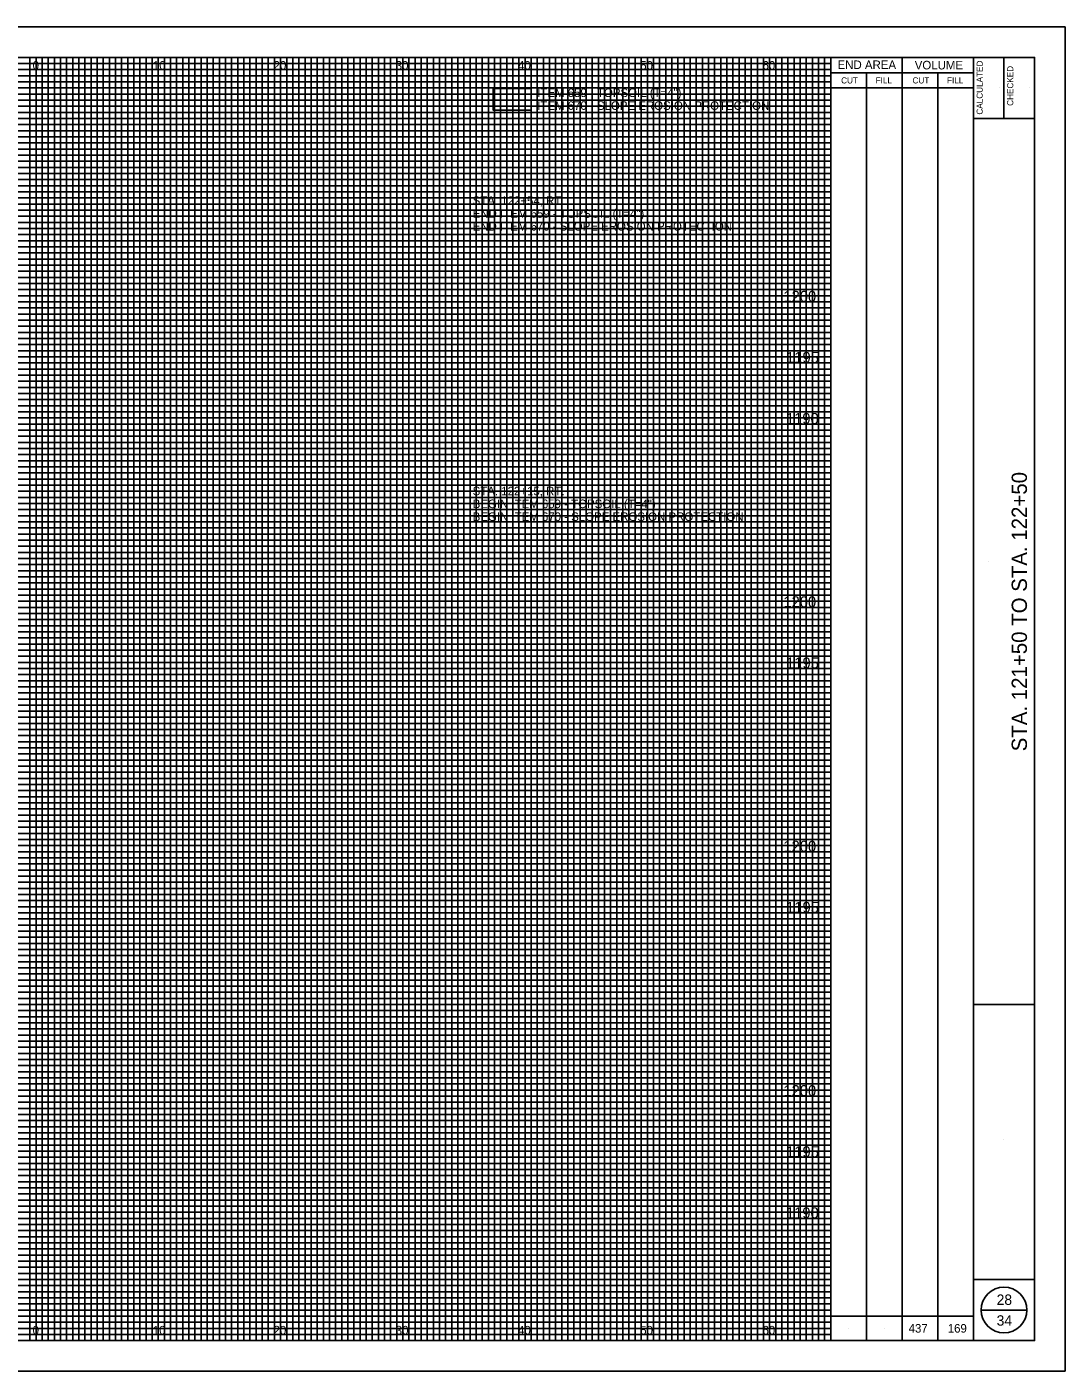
# Model space of a CAD drawing. Extents: x -10 to 160, y -13 to 1488.
# Drawn here: x 75.1 to 160, y 1262.5 to 1372.5 of the extents above; entities that cross this region are included whole.
import ezdxf

# ---------------------------------------------------------------- set-up
doc = ezdxf.new("R2010")
doc.units = 0
for name, color, linetype in [('DR_X_Storm_Sewer', 7, 'Continuous'), ('GK_Cells', 7, 'Continuous'), ('PF_P_Sta_Elev_Text', 7, 'Continuous'), ('PF_X_Ground_Line', 7, 'Continuous'), ('PV_P_EOP', 7, 'Continuous'), ('PV_P_Saw_Cut_Line', 7, 'Continuous'), ('PV_P_Shoulder', 7, 'Continuous'), ('XS_P_Pavt_Layers', 7, 'Continuous')]:
    doc.layers.add(name, color=color, linetype=linetype)

msp = doc.modelspace()

# ---------------------------------------------------------------- linework, layer by layer
at = {"layer": 'GK_Cells'}
for p, q in [((152.5, 1265), (152.5, 1370)), ((155, 1370), (155, 1365)), ((152.5, 1365), (157.5, 1365)), ((152.5, 1292.5), (157.5, 1292.5)), ((152.5, 1270), (157.5, 1270))]:
    msp.add_line(p, q, dxfattribs=at)
msp.add_lwpolyline([(0, 1370), (157.5, 1370), (157.5, 1265), (0, 1265)], close=True, dxfattribs=at)
at = {"layer": 'PF_P_Sta_Elev_Text'}
msp.add_lwpolyline([(-10, 1262.5), (160, 1262.5), (160, 1372.5), (-10, 1372.5)], close=True, dxfattribs=at)
at = {"layer": 'PF_X_Ground_Line'}
for p, q in [((140.83, 1265), (140.83, 1370)), ((146.67, 1265), (146.67, 1370)), ((140.83, 1368.75), (152.5, 1368.75)), ((143.75, 1265), (143.75, 1368.75)), ((149.58, 1265), (149.58, 1368.75)), ((140.83, 1367.5), (152.5, 1367.5)), ((154.6, 1367.52), (154.6, 1367.52)), ((157.1, 1367.52), (157.1, 1367.52)), ((153.75, 1328.75), (153.75, 1328.75)), ((156.26, 1328.75), (156.26, 1328.75)), ((155, 1281.46), (155, 1281.46)), ((153.12, 1267.5), (156.88, 1267.5)), ((155, 1267.92), (155, 1267.92)), ((140.83, 1267), (152.5, 1267)), ((155, 1266.22), (155, 1266.22)), ((142.29, 1266), (142.29, 1266)), ((145.21, 1266), (145.21, 1266)), ((148.12, 1266), (148.12, 1266)), ((151.04, 1266), (151.04, 1266))]:
    msp.add_line(p, q, dxfattribs=at)
msp.add_circle((155, 1267.5), 1.87, dxfattribs=at)
at = {"layer": 'PV_P_EOP'}
for p, q in [((5.83, 1369.5), (140.83, 1369.5)), ((75.33, 1265), (75.33, 1370)), ((76.33, 1265), (76.33, 1370)), ((76.83, 1265), (76.83, 1370)), ((77.33, 1265), (77.33, 1370)), ((77.83, 1265), (77.83, 1370)), ((78.33, 1265), (78.33, 1370)), ((78.83, 1265), (78.83, 1370)), ((79.33, 1265), (79.33, 1370)), ((79.83, 1265), (79.83, 1370)), ((80.33, 1265), (80.33, 1370)), ((81.33, 1265), (81.33, 1370)), ((81.83, 1265), (81.83, 1370)), ((82.33, 1265), (82.33, 1370)), ((82.83, 1265), (82.83, 1370)), ((83.33, 1265), (83.33, 1370)), ((83.83, 1265), (83.83, 1370)), ((84.33, 1265), (84.33, 1370)), ((84.83, 1265), (84.83, 1370)), ((85.33, 1265), (85.33, 1370)), ((86.33, 1265), (86.33, 1370)), ((86.83, 1265), (86.83, 1370)), ((87.33, 1265), (87.33, 1370)), ((87.83, 1265), (87.83, 1370)), ((88.33, 1265), (88.33, 1370)), ((88.83, 1265), (88.83, 1370)), ((89.33, 1265), (89.33, 1370)), ((89.83, 1265), (89.83, 1370)), ((90.33, 1265), (90.33, 1370)), ((91.33, 1265), (91.33, 1370)), ((91.83, 1265), (91.83, 1370)), ((92.33, 1265), (92.33, 1370)), ((92.83, 1265), (92.83, 1370)), ((93.33, 1265), (93.33, 1370)), ((93.83, 1265), (93.83, 1370)), ((94.33, 1265), (94.33, 1370)), ((94.83, 1265), (94.83, 1370)), ((95.33, 1265), (95.33, 1370)), ((96.33, 1265), (96.33, 1370)), ((96.83, 1265), (96.83, 1370)), ((97.33, 1265), (97.33, 1370)), ((97.83, 1265), (97.83, 1370)), ((98.33, 1265), (98.33, 1370)), ((98.83, 1265), (98.83, 1370)), ((99.33, 1265), (99.33, 1370)), ((99.83, 1265), (99.83, 1370)), ((100.33, 1265), (100.33, 1370)), ((101.33, 1265), (101.33, 1370)), ((101.83, 1265), (101.83, 1370)), ((102.33, 1265), (102.33, 1370)), ((102.83, 1265), (102.83, 1370)), ((103.33, 1265), (103.33, 1370)), ((103.83, 1265), (103.83, 1370)), ((104.33, 1265), (104.33, 1370)), ((104.83, 1265), (104.83, 1370)), ((105.33, 1265), (105.33, 1370)), ((106.33, 1265), (106.33, 1370)), ((106.83, 1265), (106.83, 1370)), ((107.33, 1265), (107.33, 1370)), ((107.83, 1265), (107.83, 1370)), ((108.33, 1265), (108.33, 1370)), ((108.83, 1265), (108.83, 1370)), ((109.33, 1265), (109.33, 1370)), ((109.83, 1265), (109.83, 1370)), ((110.33, 1265), (110.33, 1370)), ((111.33, 1265), (111.33, 1370)), ((111.83, 1265), (111.83, 1370)), ((112.33, 1265), (112.33, 1370)), ((112.83, 1265), (112.83, 1370)), ((113.33, 1265), (113.33, 1370)), ((113.83, 1265), (113.83, 1370)), ((114.33, 1265), (114.33, 1370)), ((114.83, 1265), (114.83, 1370)), ((115.33, 1265), (115.33, 1370)), ((116.33, 1265), (116.33, 1370)), ((116.83, 1265), (116.83, 1370)), ((117.33, 1265), (117.33, 1370)), ((117.83, 1265), (117.83, 1370)), ((118.33, 1265), (118.33, 1370)), ((118.83, 1265), (118.83, 1370)), ((119.33, 1265), (119.33, 1370)), ((119.83, 1265), (119.83, 1370)), ((120.33, 1265), (120.33, 1370)), ((121.33, 1265), (121.33, 1370)), ((121.83, 1265), (121.83, 1370)), ((122.33, 1265), (122.33, 1370)), ((122.83, 1265), (122.83, 1370)), ((123.33, 1265), (123.33, 1370)), ((123.83, 1265), (123.83, 1370)), ((124.33, 1265), (124.33, 1370)), ((124.83, 1265), (124.83, 1370)), ((125.33, 1265), (125.33, 1370)), ((126.33, 1265), (126.33, 1370)), ((126.83, 1265), (126.83, 1370)), ((127.33, 1265), (127.33, 1370)), ((127.83, 1265), (127.83, 1370)), ((128.33, 1265), (128.33, 1370)), ((128.83, 1265), (128.83, 1370)), ((129.33, 1265), (129.33, 1370)), ((129.83, 1265), (129.83, 1370)), ((130.33, 1265), (130.33, 1370)), ((131.33, 1265), (131.33, 1370)), ((131.83, 1265), (131.83, 1370)), ((132.33, 1265), (132.33, 1370)), ((132.83, 1265), (132.83, 1370)), ((133.33, 1265), (133.33, 1370)), ((133.83, 1265), (133.83, 1370)), ((134.33, 1265), (134.33, 1370)), ((134.83, 1265), (134.83, 1370)), ((135.33, 1265), (135.33, 1370)), ((136.33, 1265), (136.33, 1370)), ((136.83, 1265), (136.83, 1370)), ((137.33, 1265), (137.33, 1370)), ((137.83, 1265), (137.83, 1370)), ((138.33, 1265), (138.33, 1370)), ((138.83, 1265), (138.83, 1370)), ((139.33, 1265), (139.33, 1370)), ((139.83, 1265), (139.83, 1370)), ((140.33, 1265), (140.33, 1370)), ((5.83, 1369), (140.83, 1369)), ((5.83, 1368.5), (140.83, 1368.5)), ((5.83, 1368), (140.83, 1368)), ((5.83, 1367.5), (140.83, 1367.5)), ((5.83, 1367), (140.83, 1367)), ((5.83, 1366.5), (140.83, 1366.5)), ((5.83, 1366), (140.83, 1366)), ((5.83, 1365.5), (140.83, 1365.5)), ((5.83, 1364.5), (140.83, 1364.5)), ((5.83, 1364), (140.83, 1364)), ((5.83, 1363.5), (140.83, 1363.5)), ((5.83, 1363), (140.83, 1363)), ((5.83, 1362.5), (140.83, 1362.5)), ((5.83, 1362), (140.83, 1362)), ((5.83, 1361.5), (140.83, 1361.5)), ((5.83, 1361), (140.83, 1361)), ((5.83, 1360.5), (140.83, 1360.5)), ((5.83, 1359.5), (140.83, 1359.5)), ((5.83, 1359), (140.83, 1359)), ((5.83, 1358.5), (140.83, 1358.5)), ((5.83, 1358), (140.83, 1358)), ((5.83, 1357.5), (140.83, 1357.5)), ((5.83, 1357), (140.83, 1357)), ((5.83, 1356.5), (140.83, 1356.5)), ((5.83, 1356), (140.83, 1356)), ((5.83, 1355.5), (140.83, 1355.5)), ((5.83, 1354.5), (140.83, 1354.5)), ((5.83, 1354), (140.83, 1354)), ((5.83, 1353.5), (140.83, 1353.5)), ((5.83, 1353), (140.83, 1353)), ((5.83, 1352.5), (140.83, 1352.5)), ((5.83, 1352), (140.83, 1352)), ((5.83, 1351.5), (140.83, 1351.5)), ((5.83, 1351), (140.83, 1351)), ((5.83, 1350.5), (140.83, 1350.5)), ((5.83, 1349.5), (140.83, 1349.5)), ((5.83, 1349), (140.83, 1349)), ((5.83, 1348.5), (140.83, 1348.5)), ((5.83, 1348), (140.83, 1348)), ((5.83, 1347.5), (140.83, 1347.5)), ((5.83, 1347), (140.83, 1347)), ((5.83, 1346.5), (140.83, 1346.5)), ((5.83, 1346), (140.83, 1346)), ((5.83, 1345.5), (140.83, 1345.5)), ((5.83, 1344.5), (140.83, 1344.5)), ((5.83, 1344), (140.83, 1344)), ((5.83, 1343.5), (140.83, 1343.5)), ((5.83, 1343), (140.83, 1343)), ((5.83, 1342.5), (140.83, 1342.5)), ((5.83, 1342), (140.83, 1342)), ((5.83, 1341.5), (140.83, 1341.5)), ((5.83, 1341), (140.83, 1341)), ((5.83, 1340.5), (140.83, 1340.5)), ((5.83, 1339.5), (140.83, 1339.5)), ((5.83, 1339), (140.83, 1339)), ((5.83, 1338.5), (140.83, 1338.5)), ((5.83, 1338), (140.83, 1338)), ((5.83, 1337.5), (140.83, 1337.5)), ((5.83, 1337), (140.83, 1337)), ((5.83, 1336.5), (140.83, 1336.5)), ((5.83, 1336), (140.83, 1336)), ((5.83, 1335.5), (140.83, 1335.5)), ((5.83, 1334.5), (140.83, 1334.5)), ((5.83, 1334), (140.83, 1334)), ((5.83, 1333.5), (140.83, 1333.5)), ((5.83, 1333), (140.83, 1333)), ((5.83, 1332.5), (140.83, 1332.5)), ((5.83, 1332), (140.83, 1332)), ((5.83, 1331.5), (140.83, 1331.5)), ((5.83, 1331), (140.83, 1331)), ((5.83, 1330.5), (140.83, 1330.5)), ((5.83, 1329.5), (140.83, 1329.5)), ((5.83, 1329), (140.83, 1329)), ((5.83, 1328.5), (140.83, 1328.5)), ((5.83, 1328), (140.83, 1328)), ((5.83, 1327.5), (140.83, 1327.5)), ((5.83, 1327), (140.83, 1327)), ((5.83, 1326.5), (140.83, 1326.5)), ((5.83, 1326), (140.83, 1326)), ((5.83, 1325.5), (140.83, 1325.5)), ((5.83, 1324.5), (140.83, 1324.5)), ((5.83, 1324), (140.83, 1324)), ((5.83, 1323.5), (140.83, 1323.5)), ((5.83, 1323), (140.83, 1323)), ((5.83, 1322.5), (140.83, 1322.5)), ((5.83, 1322), (140.83, 1322)), ((5.83, 1321.5), (140.83, 1321.5)), ((5.83, 1321), (140.83, 1321)), ((5.83, 1320.5), (140.83, 1320.5)), ((5.83, 1319.5), (140.83, 1319.5)), ((5.83, 1319), (140.83, 1319)), ((5.83, 1318.5), (140.83, 1318.5)), ((5.83, 1318), (140.83, 1318)), ((5.83, 1317.5), (140.83, 1317.5)), ((5.83, 1317), (140.83, 1317)), ((5.83, 1316.5), (140.83, 1316.5)), ((5.83, 1316), (140.83, 1316)), ((5.83, 1315.5), (140.83, 1315.5)), ((5.83, 1314.5), (140.83, 1314.5)), ((5.83, 1314), (140.83, 1314)), ((5.83, 1313.5), (140.83, 1313.5)), ((5.83, 1313), (140.83, 1313)), ((5.83, 1312.5), (140.83, 1312.5)), ((5.83, 1312), (140.83, 1312)), ((5.83, 1311.5), (140.83, 1311.5)), ((5.83, 1311), (140.83, 1311)), ((5.83, 1310.5), (140.83, 1310.5)), ((5.83, 1309.5), (140.83, 1309.5)), ((5.83, 1309), (140.83, 1309)), ((5.83, 1308.5), (140.83, 1308.5)), ((5.83, 1308), (140.83, 1308)), ((5.83, 1307.5), (140.83, 1307.5)), ((5.83, 1307), (140.83, 1307)), ((5.83, 1306.5), (140.83, 1306.5)), ((5.83, 1306), (140.83, 1306)), ((5.83, 1305.5), (140.83, 1305.5)), ((5.83, 1304.5), (140.83, 1304.5)), ((5.83, 1304), (140.83, 1304)), ((5.83, 1303.5), (140.83, 1303.5)), ((5.83, 1303), (140.83, 1303)), ((5.83, 1302.5), (140.83, 1302.5)), ((5.83, 1302), (140.83, 1302)), ((5.83, 1301.5), (140.83, 1301.5)), ((5.83, 1301), (140.83, 1301)), ((5.83, 1300.5), (140.83, 1300.5)), ((5.83, 1299.5), (140.83, 1299.5)), ((5.83, 1299), (140.83, 1299)), ((5.83, 1298.5), (140.83, 1298.5)), ((5.83, 1298), (140.83, 1298)), ((5.83, 1297.5), (140.83, 1297.5)), ((5.83, 1297), (140.83, 1297)), ((5.83, 1296.5), (140.83, 1296.5)), ((5.83, 1296), (140.83, 1296)), ((5.83, 1295.5), (140.83, 1295.5)), ((5.83, 1294.5), (140.83, 1294.5)), ((5.83, 1294), (140.83, 1294)), ((5.83, 1293.5), (140.83, 1293.5)), ((5.83, 1293), (140.83, 1293)), ((5.83, 1292.5), (140.83, 1292.5)), ((5.83, 1292), (140.83, 1292)), ((5.83, 1291.5), (140.83, 1291.5)), ((5.83, 1291), (140.83, 1291)), ((5.83, 1290.5), (140.83, 1290.5)), ((5.83, 1289.5), (140.83, 1289.5)), ((5.83, 1289), (140.83, 1289)), ((5.83, 1288.5), (140.83, 1288.5)), ((5.83, 1288), (140.83, 1288)), ((5.83, 1287.5), (140.83, 1287.5)), ((5.83, 1287), (140.83, 1287)), ((5.83, 1286.5), (140.83, 1286.5)), ((5.83, 1286), (140.83, 1286)), ((5.83, 1285.5), (140.83, 1285.5)), ((5.83, 1284.5), (140.83, 1284.5)), ((5.83, 1284), (140.83, 1284)), ((5.83, 1283.5), (140.83, 1283.5)), ((5.83, 1283), (140.83, 1283)), ((5.83, 1282.5), (140.83, 1282.5)), ((5.83, 1282), (140.83, 1282)), ((5.83, 1281.5), (140.83, 1281.5)), ((5.83, 1281), (140.83, 1281)), ((5.83, 1280.5), (140.83, 1280.5)), ((5.83, 1279.5), (140.83, 1279.5)), ((5.83, 1279), (140.83, 1279)), ((5.83, 1278.5), (140.83, 1278.5)), ((5.83, 1278), (140.83, 1278)), ((5.83, 1277.5), (140.83, 1277.5)), ((5.83, 1277), (140.83, 1277)), ((5.83, 1276.5), (140.83, 1276.5)), ((5.83, 1276), (140.83, 1276)), ((5.83, 1275.5), (140.83, 1275.5)), ((5.83, 1274.5), (140.83, 1274.5)), ((5.83, 1274), (140.83, 1274)), ((5.83, 1273.5), (140.83, 1273.5)), ((5.83, 1273), (140.83, 1273)), ((5.83, 1272.5), (140.83, 1272.5)), ((5.83, 1272), (140.83, 1272)), ((5.83, 1271.5), (140.83, 1271.5)), ((5.83, 1271), (140.83, 1271)), ((5.83, 1270.5), (140.83, 1270.5)), ((5.83, 1269.5), (140.83, 1269.5)), ((5.83, 1269), (140.83, 1269)), ((5.83, 1268.5), (140.83, 1268.5)), ((5.83, 1268), (140.83, 1268)), ((5.83, 1267.5), (140.83, 1267.5)), ((5.83, 1267), (140.83, 1267)), ((5.83, 1266.5), (140.83, 1266.5)), ((5.83, 1266), (140.83, 1266)), ((5.83, 1265.5), (140.83, 1265.5))]:
    msp.add_line(p, q, dxfattribs=at)
at = {"layer": 'PV_P_Saw_Cut_Line'}
msp.add_lwpolyline([(113.21, 1367.47), (116.32, 1367.47), (116.32, 1365.69), (113.21, 1365.69)], close=True, dxfattribs=at)
msp.add_lwpolyline([(113.21, 1365.69), (116.32, 1365.69), (116.32, 1367.47), (113.21, 1367.47), (113.21, 1365.69)], dxfattribs=at)
at = {"layer": 'PV_P_Shoulder'}
for p, q in [((75.83, 1265), (75.83, 1370)), ((80.83, 1265), (80.83, 1370)), ((85.83, 1265), (85.83, 1370)), ((90.83, 1265), (90.83, 1370)), ((95.83, 1265), (95.83, 1370)), ((100.83, 1265), (100.83, 1370)), ((105.83, 1265), (105.83, 1370)), ((110.83, 1265), (110.83, 1370)), ((115.83, 1265), (115.83, 1370)), ((120.83, 1265), (120.83, 1370)), ((125.83, 1265), (125.83, 1370)), ((130.83, 1265), (130.83, 1370)), ((135.83, 1265), (135.83, 1370)), ((11.66, 1365), (140.83, 1365)), ((11.66, 1360), (140.83, 1360)), ((11.66, 1355), (140.83, 1355)), ((11.66, 1350), (140.83, 1350)), ((11.66, 1345), (140.83, 1345)), ((11.66, 1340), (140.83, 1340)), ((11.66, 1335), (140.83, 1335)), ((11.66, 1330), (140.83, 1330)), ((11.66, 1325), (140.83, 1325)), ((11.66, 1320), (140.83, 1320)), ((11.66, 1315), (140.83, 1315)), ((11.66, 1310), (140.83, 1310)), ((11.66, 1305), (140.83, 1305)), ((11.66, 1300), (140.83, 1300)), ((11.66, 1295), (140.83, 1295)), ((11.66, 1290), (140.83, 1290)), ((11.66, 1285), (140.83, 1285)), ((11.66, 1280), (140.83, 1280)), ((11.66, 1275), (140.83, 1275)), ((11.66, 1270), (140.83, 1270))]:
    msp.add_line(p, q, dxfattribs=at)

# ---------------------------------------------------------------- texts
at = {"layer": 'DR_X_Storm_Sewer'}
for s, height, p in [('0', 0.7, (75.55, 1369)), ('0', 0.7, (75.55, 1369)), ('10', 0.7, (85.39, 1369)), ('20', 0.7, (95.26, 1369)), ('30', 0.7, (105.25, 1369)), ('40', 0.7, (115.25, 1369)), ('50', 0.7, (125.25, 1369)), ('60', 0.7, (135.25, 1369)), ('1200', 0.9, (136.96, 1350)), ('1195', 0.9, (137.18, 1345)), ('1190', 0.9, (137.17, 1340)), ('1200', 0.9, (136.96, 1325)), ('1195', 0.9, (137.18, 1320)), ('1200', 0.9, (136.96, 1305)), ('1195', 0.9, (137.18, 1300)), ('1200', 0.9, (136.96, 1285)), ('1195', 0.9, (137.18, 1280)), ('1190', 0.9, (137.17, 1275)), ('28', 0.85, (154.4, 1267.92)), ('0', 0.7, (75.55, 1265.5)), ('0', 0.7, (75.55, 1265.5)), ('10', 0.7, (85.39, 1265.5)), ('20', 0.7, (95.26, 1265.5)), ('30', 0.7, (105.25, 1265.5)), ('40', 0.7, (115.25, 1265.5)), ('50', 0.7, (125.25, 1265.5)), ('60', 0.7, (135.25, 1265.5)), ('437', 0.7, (147.2, 1265.65)), ('169', 0.7, (150.4, 1265.65)), ('34', 0.85, (154.4, 1266.22))]:
    msp.add_text(s, height=height, dxfattribs=at).set_placement(p)
at = {"layer": 'PF_X_Ground_Line'}
for s, height, p in [('END AREA', 0.7, (141.39, 1369.05)), ('VOLUME', 0.7, (147.7, 1369.02)), ('CUT', 0.5, (141.68, 1367.87)), ('FILL', 0.5, (144.5, 1367.87)), ('CUT', 0.5, (147.52, 1367.87)), ('FILL', 0.5, (150.34, 1367.87))]:
    msp.add_text(s, height=height, dxfattribs=at).set_placement(p)
for s, height, p in [('CALCULATED', 0.5, (153.26, 1365.32)), ('CHECKED', 0.5, (155.76, 1366.04)), ('STA. 121+50 TO STA. 122+50', 1.25, (156.88, 1313.22))]:
    msp.add_text(s, height=height, rotation=90, dxfattribs=at).set_placement(p)
at = {"layer": 'XS_P_Pavt_Layers'}
for s, p in [('ITEM 659 - TOPSOIL (T=4")', (116.82, 1366.76)), ('ITEM 670 - SLOPE EROSION PROTECTION', (116.82, 1365.71)), ('STA. 122+54, RT.', (111.54, 1357.93)), ('END ITEM 659 - TOPSOIL (T=4")', (111.54, 1356.88)), ('END ITEM 670 - SLOPE EROSION PROTECTION', (111.54, 1355.83)), ('STA. 122+15, RT.', (111.54, 1334.17)), ('BEGIN ITEM 659 - TOPSOIL (T=4")', (111.54, 1333.12)), ('BEGIN ITEM 670 - SLOPE EROSION PROTECTION', (111.54, 1332.07))]:
    msp.add_text(s, height=0.7, dxfattribs=at).set_placement(p)

doc.saveas('drawing.dxf')
